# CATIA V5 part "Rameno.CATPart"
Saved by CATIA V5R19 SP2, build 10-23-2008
Part number: Rameno
Bounding box of the stored display mesh (mm): x -70 to 70, y -245.484 to 40, z 0 to 40
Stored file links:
  D:\Catia\Flexible-rigid\Rameno.CATPart
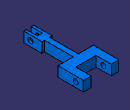
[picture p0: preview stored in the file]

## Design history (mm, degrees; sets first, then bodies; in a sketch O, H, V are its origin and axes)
AxisSystem1: origin (0, 0, 0), X (1, 0, 0), Y (0, 1, 0), Z (0, 0, 1)
Set1
  Sketch1 on XY plane of AxisSystem1, origin (0, 0, 0), H (1, 0, 0), V (0, 1, 0)
    line L1 (-40, 40) -> (-40, -20)
    line L2 (-40, -20) -> (0, -20)
    line L3 (0, -20) -> (0, -201.7651)
    line L4 (0, -201.7651) -> (-10, -201.7651)
    line L5 (-10, -201.7651) -> (-10, -245.4839)
    line L6 (-10, -245.4839) -> (-20, -245.4839)
    line L7 (-20, -245.4839) -> (-20, -173.7188)
    line L8 (-20, -173.7188) -> (-10, -173.7188)
    point P9 (-10, -173.7188)
    line L9 (-10, -173.7188) -> (-10, -60)
    line L10 (-10, -60) -> (-70, -60)
    line L11 (-70, -60) -> (-70, 40)
    line L12 (-70, 40) -> (-40, 40)
    vertical: L1 V, L3 V, L5 V, L7 V, L9 V, L11 V
    horizontal: L2 H, L4 H, L6 H, L8 H, L10 H, L12 H
    coincidence: P9 L5
Body1 (main body)
  Pad1: profile Sketch1, direction (0, 0, 1), length 40
  Sketch2 on face of Pad1 from Sketch1.L1, origin (-40, 9.1227, 19.4151), H (0, 1, 0), V (0, 0, 1)
    point P1 (0, 0)
  Hole1: placed by Sketch2, at (-40, 9.1227, 19.4151) direction (-1, 0, 0), diameter 20, through (limit type 6)
  Sketch3 on face of Pad1 from Sketch1.L5, origin (-10, -219.248, 20.752), H (0, 1, 0), V (0, 0, 1)
    point P1 (0, 0)
  Hole2: placed by Sketch3, at (-10, -219.248, 20.752) direction (-1, 0, 0), diameter 20, through (limit type 6)
  Mirror1: of the body so far, about face of Pad1 from Sketch1.L3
